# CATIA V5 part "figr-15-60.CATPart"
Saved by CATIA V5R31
Part number: Part1
Bounding box of the stored display mesh (mm): x -35.944 to 35.944, y -33.497 to 33.497, z 0 to 50.428
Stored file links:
  D:\PROJECTS\Project 2021\US EDITION\CATIA V5 6R 2021\Resources\Part Files\c15_catia_v5_6r2021_prt\figr-15-60.CATPart
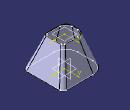
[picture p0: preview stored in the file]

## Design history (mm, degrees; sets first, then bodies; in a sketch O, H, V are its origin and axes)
SheetMetalParameters1: Thickness 1, BendRadius 2, KFactor 0.400515 {= log(min(100,max(20*SheetMetalParameters1.BendRadius,SheetMetalParameters1.Thickness)/SheetMetalParameters1.Thickness))/log(100)/2}, ReliefRadialLength 1, ReliefAxialLength 2, MinimumBendRadius 0
Body1 (main body)
  Sketch1 on xy-plane, origin (0, 0, 0), H (1, 0, 0), V (0, 1, 0)
    line L1 (-15, -32.5532) -> (30, -32.5532)
    line L2 (35, -27.5532) -> (35, 27.5532)
    line L3 (30, 32.5532) -> (-15, 32.5532)
    line L4 (-35, 12.5532) -> (-35, -12.5532)
    arc A1 centre (-15, -12.5532) radius 20 from (-35, -12.5532) to (-15, -32.5532) ccw
    arc A2 centre (-15, 12.5532) radius 20 from (-35, 12.5532) to (-15, 32.5532) cw
    arc A3 centre (30, -27.5532) radius 5 from (30, -32.5532) to (35, -27.5532) ccw
    arc A4 centre (30, 27.5532) radius 5 from (35, 27.5532) to (30, 32.5532) ccw
    radius A1 = 20
    radius A2 = 20
    radius A3 = 5
    radius A4 = 5
    distance L2 L4 = 70
    horizontal: L1 H, L3 H
    vertical: L2 V, L4 V
    tangency: A1 L4, A1 L1, A2 L4, A2 L3, A3 L1, A3 L2, A4 L2, A4 L3
    symmetry: L3 L1 H, L4 L2 V
  Plane1: type Offset, RefPlane xy-plane, Offset 50
  Sketch2 "Sketch.2" on Plane1, origin (0, 0, 50), H (1, 0, 0), V (0, 1, 0)
    line L1 (-7.5, 15) -> (14.5, 15)
    line L2 (17.5, 12) -> (17.5, -12)
    line L3 (14.5, -15) -> (-7.5, -15)
    line L4 (-17.5, -5) -> (-17.5, 5)
    arc A1 centre (-7.5, -5) radius 10 from (-7.5, -15) to (-17.5, -5) cw
    arc A2 centre (-7.5, 5) radius 10 from (-17.5, 5) to (-7.5, 15) cw
    arc A3 centre (14.5, 12) radius 3 from (14.5, 15) to (17.5, 12) cw
    arc A4 centre (14.5, -12) radius 3 from (17.5, -12) to (14.5, -15) cw
    radius A1 = 10
    radius A2 = 10
    radius A3 = 3
    radius A4 = 3
    distance L4 L2 = 35
    distance L1 L3 = 30
    horizontal: L1 H, L3 H
    vertical: L2 V, L4 V
    tangency: A1 L3, A1 L4, A2 L4, A2 L1, A3 L1, A3 L2, A4 L2, A4 L3
    symmetry: L4 L2 V, L1 L3 H
  Hopper1: KFacteur 0.400515 {= SheetMetalParameters1.KFactor}, HopperFixedSideType 0, HopperType 0, Hopper_InvariantPoint vertex [element of Sketch1 | element of Sketch1], Hopper_NeutralFiber 0, Hopper_ReferenceEdge edge [face of Hopper1 | face of Hopper1], Hopper_Surface {loft Sections (Sketch1; Sketch2), SectionCouplingPoints ({coupling CouplingPoints (vertex [element of Sketch1 | element of Sketch1]; vertex [element of Sketch2 | element of Sketch2])}; {coupling CouplingPoints (vertex [element of Sketch1 | element of Sketch1]; vertex [element of Sketch2 | element of Sketch2])}; {coupling CouplingPoints (vertex [element of Sketch1 | element of Sketch1]; vertex [element of Sketch2 | element of Sketch2])}; {coupling CouplingPoints (vertex [element of Sketch1 | element of Sketch1]; vertex [element of Sketch2 | element of Sketch2])}; {coupling CouplingPoints (vertex [element of Sketch1 | element of Sketch1]; vertex [element of Sketch2 | element of Sketch2])}; {coupling CouplingPoints (vertex [element of Sketch1 | element of Sketch1]; vertex [element of Sketch2 | element of Sketch2])}; {coupling CouplingPoints (vertex [element of Sketch1 | element of Sketch1]; vertex [element of Sketch2 | element of Sketch2])}; {coupling CouplingPoints (vertex [element of Sketch1 | element of Sketch1]; vertex [element of Sketch2 | element of Sketch2])})}, Hopper_TearWires edge [face of Hopper1 | face of Hopper1], Hopper_Thickness 1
